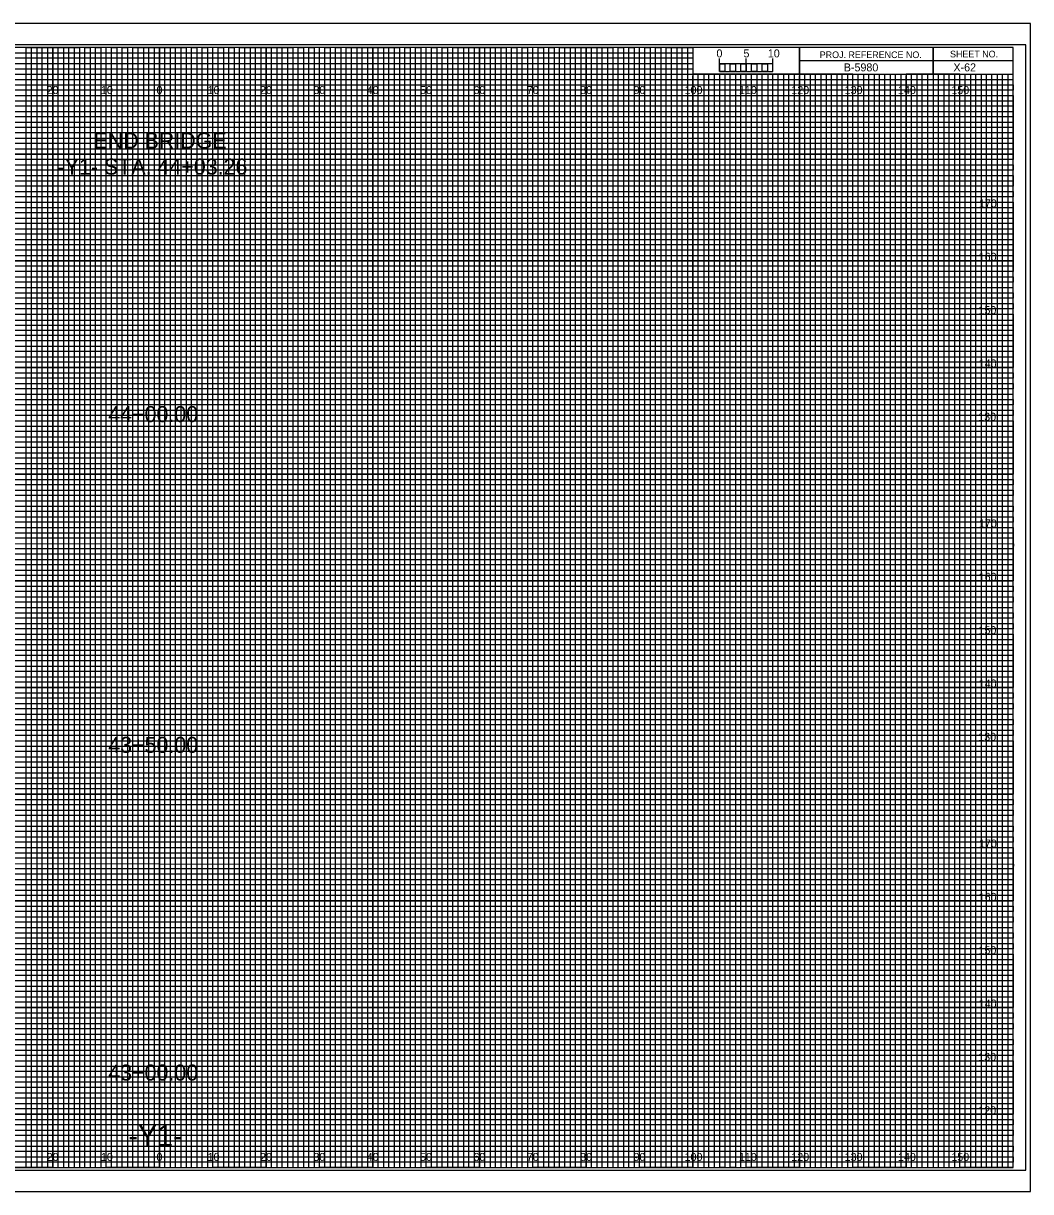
# Model space of a CAD drawing. Extents: x -13 to 323, y -5 to 4834.
# Drawn here: x 134.5 to 323.3, y 3515.5 to 3734.5 of the extents above; entities that cross this region are included whole.
import ezdxf

# ---------------------------------------------------------------- set-up
doc = ezdxf.new("R2010")
doc.units = 0
for name, color, linetype in [('Exist CMT Pavement', 7, 'Continuous'), ('Exist Cross Section Cell', 7, 'Continuous'), ('Exist XS Center Line Elevation Label', 7, 'Continuous'), ('Exist XS Ground Line', 7, 'Continuous'), ('Prop CMT Pvmt Course 1', 7, 'Continuous'), ('Prop CMT Pvmt Course 1 Wedge', 7, 'Continuous'), ('Prop CMT Pvmt Course 2', 7, 'Continuous'), ('Prop CMT Pvmt Course 2 Wedge', 7, 'Continuous'), ('Prop CMT Pvmt Course 3', 7, 'Continuous'), ('Prop CMT Pvmt Course 3 Wedge', 7, 'Continuous'), ('Prop CMT Pvmt Surface', 7, 'Continuous'), ('Prop CMT Pvmt Surface Shoulder', 7, 'Continuous'), ('Prop CMT Shld Paved Course 1', 7, 'Continuous'), ('Prop CMT Shld Paved Course 2', 7, 'Continuous'), ('Prop CMT Shld Paved Course 3', 7, 'Continuous'), ('Prop CMT Slope Grass', 7, 'Continuous'), ('Prop CMT Subgrade Earthwork', 7, 'Continuous')]:
    doc.layers.add(name, color=color, linetype=linetype)

msp = doc.modelspace()

# ---------------------------------------------------------------- linework, layer by layer
at = {"layer": 'Exist XS Center Line Elevation Label'}
for points in [[(125, 3520), (135, 3520), (135, 3730), (145, 3730), (145, 3520), (155, 3520), (155, 3730), (165, 3730), (165, 3520), (175, 3520), (175, 3730), (185, 3730), (185, 3520), (195, 3520), (195, 3730), (205, 3730), (205, 3520), (215, 3520), (215, 3730), (225, 3730), (225, 3520), (235, 3520), (235, 3730), (245, 3730), (245, 3520), (255, 3520), (255, 3730), (259.93, 3730), (260, 3730), (260, 3725), (264.99, 3725), (264.99, 3520), (275, 3520), (275, 3725), (285, 3725), (285, 3520), (295, 3520), (295, 3725), (305, 3725), (305, 3520), (315, 3520), (315, 3725)], [(0, 3725), (275, 3725)], [(0, 3705), (320, 3705), (320, 3715), (0, 3715)], [(0, 3685), (320, 3685), (320, 3695), (0, 3695)], [(0, 3665), (320, 3665), (320, 3675), (0, 3675)], [(0, 3645), (320, 3645), (320, 3655), (0, 3655)], [(0, 3625), (320, 3625), (320, 3635), (0, 3635)], [(0, 3605), (320, 3605), (320, 3615), (0, 3615)], [(0, 3585), (320, 3585), (320, 3595), (0, 3595)], [(0, 3565), (320, 3565), (320, 3575), (0, 3575)], [(0, 3545), (320, 3545), (320, 3555), (0, 3555)], [(0, 3525), (320, 3525), (320, 3535), (0, 3535)]]:
    msp.add_lwpolyline(points, dxfattribs=at)
at = {"layer": 'Exist XS Ground Line'}
for p, q in [((150, 3730), (140, 3730)), ((140, 3730), (140, 3520)), ((150, 3520), (150, 3730)), ((170, 3730), (160, 3730)), ((160, 3730), (160, 3520)), ((170, 3520), (170, 3730)), ((190, 3730), (180, 3730)), ((180, 3730), (180, 3520)), ((190, 3520), (190, 3730)), ((210, 3730), (200, 3730)), ((200, 3730), (200, 3520)), ((210, 3520), (210, 3730)), ((230, 3730), (220, 3730)), ((220, 3730), (220, 3520)), ((230, 3520), (230, 3730)), ((250, 3730), (240, 3730)), ((240, 3730), (240, 3520)), ((250, 3520), (250, 3730)), ((260, 3730), (260, 3520)), ((270, 3520), (270, 3725)), ((290, 3725), (280, 3725)), ((280, 3725), (280, 3520)), ((290, 3520), (290, 3725)), ((310, 3725), (300, 3725)), ((300, 3725), (300, 3520)), ((310, 3520), (310, 3725)), ((140, 3520), (130, 3520)), ((160, 3520), (150, 3520)), ((180, 3520), (170, 3520)), ((200, 3520), (190, 3520)), ((220, 3520), (210, 3520)), ((240, 3520), (230, 3520)), ((260, 3520), (250, 3520)), ((280, 3520), (270, 3520)), ((300, 3520), (290, 3520)), ((320, 3520), (310, 3520)), ((320, 3520), (320, 3520))]:
    msp.add_line(p, q, dxfattribs=at)
for points in [[(0, 3720), (320, 3720), (320, 3710), (0, 3710)], [(0, 3700), (320, 3700), (320, 3690), (0, 3690)], [(0, 3680), (320, 3680), (320, 3670), (0, 3670)], [(0, 3660), (320, 3660), (320, 3650), (0, 3650)], [(0, 3640), (320, 3640), (320, 3630), (0, 3630)], [(0, 3620), (320, 3620), (320, 3610), (0, 3610)], [(0, 3600), (320, 3600), (320, 3590), (0, 3590)], [(0, 3580), (320, 3580), (320, 3570), (0, 3570)], [(0, 3560), (320, 3560), (320, 3550), (0, 3550)], [(0, 3540), (320, 3540), (320, 3530), (0, 3530)]]:
    msp.add_lwpolyline(points, dxfattribs=at)
at = {"layer": 'Prop CMT Pvmt Course 1'}
for p, q in [((267, 3725), (266.01, 3725)), ((266.01, 3725), (266.01, 3520)), ((267, 3520), (267, 3725)), ((269, 3725), (268, 3725)), ((268, 3725), (268, 3520)), ((269, 3520), (269, 3725)), ((266.01, 3520), (265, 3520)), ((268, 3520), (267, 3520))]:
    msp.add_line(p, q, dxfattribs=at)
for points in [[(135, 3520), (136, 3520), (136, 3730), (137, 3730), (137, 3520)], [(137, 3520), (138, 3520), (138, 3730), (139, 3730), (139, 3520)], [(140, 3520), (141, 3520), (141, 3730), (142, 3730), (142, 3520)], [(142, 3520), (143, 3520), (143, 3730), (144, 3730), (144, 3520)], [(145, 3520), (146, 3520), (146, 3730), (147, 3730), (147, 3520)], [(147, 3520), (148, 3520), (148, 3730), (149, 3730), (149, 3520)], [(150, 3520), (151, 3520), (151, 3730), (152, 3730), (152, 3520)], [(152, 3520), (153, 3520), (153, 3730), (154, 3730), (154, 3520)], [(155, 3520), (156, 3520), (156, 3730), (157, 3730), (157, 3520)], [(157, 3520), (158, 3520), (158, 3730), (159, 3730), (159, 3520)], [(160, 3520), (161, 3520), (161, 3730), (162, 3730), (162, 3520)], [(162, 3520), (163, 3520), (163, 3730), (164, 3730), (164, 3520)], [(165, 3520), (166, 3520), (166, 3730), (167, 3730), (167, 3520)], [(167, 3520), (168, 3520), (168, 3730), (169, 3730), (169, 3520)], [(170, 3520), (171, 3520), (171, 3730), (172, 3730), (172, 3520)], [(172, 3520), (173, 3520), (173, 3730), (174, 3730), (174, 3520)], [(175, 3520), (176, 3520), (176, 3730), (177, 3730), (177, 3520)], [(177, 3520), (178, 3520), (178, 3730), (179, 3730), (179, 3520)], [(180, 3520), (181, 3520), (181, 3730), (182, 3730), (182, 3520)], [(182, 3520), (183, 3520), (183, 3730), (184, 3730), (184, 3520)], [(185, 3520), (186, 3520), (186, 3730), (187, 3730), (187, 3520)], [(187, 3520), (188, 3520), (188, 3730), (189, 3730), (189, 3520)], [(190, 3520), (191, 3520), (191, 3730), (192, 3730), (192, 3520)], [(192, 3520), (193, 3520), (193, 3730), (194, 3730), (194, 3520)], [(195, 3520), (196, 3520), (196, 3730), (197, 3730), (197, 3520)], [(197, 3520), (198, 3520), (198, 3730), (199, 3730), (199, 3520)], [(200, 3520), (201, 3520), (201, 3730), (202, 3730), (202, 3520)], [(202, 3520), (203, 3520), (203, 3730), (204, 3730), (204, 3520)], [(205, 3520), (206, 3520), (206, 3730), (207, 3730), (207, 3520)], [(207, 3520), (208, 3520), (208, 3730), (209, 3730), (209, 3520)], [(210, 3520), (211, 3520), (211, 3730), (212, 3730), (212, 3520)], [(212, 3520), (213, 3520), (213, 3730), (214, 3730), (214, 3520)], [(215, 3520), (216, 3520), (216, 3730), (217, 3730), (217, 3520)], [(217, 3520), (218, 3520), (218, 3730), (219, 3730), (219, 3520)], [(220, 3520), (221, 3520), (221, 3730), (222, 3730), (222, 3520)], [(222, 3520), (223, 3520), (223, 3730), (224, 3730), (224, 3520)], [(225, 3520), (226, 3520), (226, 3730), (227, 3730), (227, 3520)], [(227, 3520), (228, 3520), (228, 3730), (229, 3730), (229, 3520)], [(230, 3520), (231, 3520), (231, 3730), (232, 3730), (232, 3520)], [(232, 3520), (233, 3520), (233, 3730), (234, 3730), (234, 3520)], [(235, 3520), (236, 3520), (236, 3730), (237, 3730), (237, 3520)], [(237, 3520), (238, 3520), (238, 3730), (239, 3730), (239, 3520)], [(240, 3520), (241, 3520), (241, 3730), (242, 3730), (242, 3520)], [(242, 3520), (243, 3520), (243, 3730), (244, 3730), (244, 3520)], [(245, 3520), (246, 3520), (246, 3730), (247, 3730), (247, 3520)], [(247, 3520), (248, 3520), (248, 3730), (249, 3730), (249, 3520)], [(250, 3520), (251, 3520), (251, 3730), (252, 3730), (252, 3520)], [(252, 3520), (253, 3520), (253, 3730), (254, 3730), (254, 3520)], [(255, 3520), (256, 3520), (256, 3730), (257, 3730), (257, 3520)], [(257, 3520), (258, 3520), (258, 3730), (259, 3730), (259, 3520)], [(260, 3520), (261, 3520), (261, 3725), (262.02, 3725), (262.02, 3520)], [(262, 3520), (263, 3520), (263, 3725), (263.99, 3725), (263.99, 3520)], [(270, 3520), (270.98, 3520), (270.98, 3725), (272, 3725), (272, 3520)], [(272, 3520), (273, 3520), (273, 3725), (274.05, 3725), (274.05, 3520)], [(275, 3520), (276, 3520), (276, 3725), (277, 3725), (277, 3520)], [(277, 3520), (278, 3520), (278, 3725), (279, 3725), (279, 3520)], [(280, 3520), (281, 3520), (281, 3725), (282, 3725), (282, 3520)], [(282, 3520), (283, 3520), (283, 3725), (284, 3725), (284, 3520)], [(285, 3520), (286, 3520), (286, 3725), (287, 3725), (287, 3520)], [(287, 3520), (288, 3520), (288, 3725), (289, 3725), (289, 3520)], [(290, 3520), (291, 3520), (291, 3725), (292, 3725), (292, 3520)], [(292, 3520), (293, 3520), (293, 3725), (294, 3725), (294, 3520)], [(295, 3520), (296, 3520), (296, 3725), (297, 3725), (297, 3520)], [(297, 3520), (298, 3520), (298, 3725), (299, 3725), (299, 3520)], [(300, 3520), (301, 3520), (301, 3725), (302, 3725), (302, 3520)], [(302, 3520), (303, 3520), (303, 3725), (304, 3725), (304, 3520)], [(305, 3520), (306, 3520), (306, 3725), (307, 3725), (307, 3520)], [(307, 3520), (308, 3520), (308, 3725), (309, 3725), (309, 3520)], [(310, 3520), (311, 3520), (311, 3725), (312, 3725), (312, 3520)], [(312, 3520), (313, 3520), (313, 3725), (314, 3725), (314, 3520)], [(315, 3520), (316, 3520), (316, 3725), (317, 3725), (317, 3520)], [(317, 3520), (318, 3520), (318, 3725), (319, 3725), (319, 3520)]]:
    msp.add_lwpolyline(points, dxfattribs=at)
at = {"layer": 'Prop CMT Pvmt Course 2'}
for p, q in [((323.3, 3734.5), (-13.4, 3734.5)), ((-13.4, 3515.5), (323.3, 3515.5))]:
    msp.add_line(p, q, dxfattribs=at)
at = {"layer": 'Prop CMT Pvmt Surface Shoulder'}
for p, q in [((305, 3730), (305, 3725)), ((305, 3725), (305, 3730)), ((280, 3727.5), (280, 3725)), ((320, 3727.49), (280, 3727.49)), ((280, 3725), (320, 3725))]:
    msp.add_line(p, q, dxfattribs=at)
for points in [[(320, 3730), (0, 3730), (0, 3520), (320, 3520)], [(280, 3730), (260, 3730), (260, 3725.03), (280, 3725.03)], [(320, 3730), (280, 3730), (280, 3725), (320, 3725)]]:
    msp.add_lwpolyline(points, close=True, dxfattribs=at)
at = {"layer": 'Prop CMT Shld Paved Course 1'}
msp.add_lwpolyline([(-13.4, 3515.5), (323.3, 3515.5), (323.3, 3734.5), (-13.4, 3734.5)], close=True, dxfattribs=at)
at = {"layer": 'Prop CMT Shld Paved Course 2'}
msp.add_lwpolyline([(-10.8, 3519.5), (322.4, 3519.5), (322.4, 3730.5), (-10.8, 3730.5)], close=True, dxfattribs=at)
at = {"layer": 'Prop CMT Shld Paved Course 3'}
for p, q in [((140, 3520), (140, 3730)), ((150, 3520), (150, 3730)), ((160, 3520), (160, 3730)), ((170, 3520), (170, 3730)), ((180, 3520), (180, 3730)), ((190, 3520), (190, 3730)), ((200, 3520), (200, 3730)), ((210, 3520), (210, 3730)), ((220, 3520), (220, 3730)), ((230, 3520), (230, 3730)), ((240, 3520), (240, 3730)), ((250, 3520), (250, 3730)), ((260, 3520), (260, 3724.69)), ((270, 3520), (270, 3724.69)), ((280, 3520), (280, 3724.69)), ((290, 3520), (290, 3724.69)), ((300, 3520), (300, 3724.69)), ((310, 3520), (310, 3724.69)), ((0, 3720), (320, 3720)), ((0, 3710), (320, 3710)), ((0, 3700), (320, 3700)), ((0, 3690), (320, 3690)), ((0, 3680), (320, 3680)), ((0, 3670), (320, 3670)), ((0, 3660), (320, 3660)), ((0, 3650), (320, 3650)), ((0, 3640), (320, 3640)), ((0, 3630), (320, 3630)), ((0, 3620), (320, 3620)), ((0, 3610), (320, 3610)), ((0, 3600), (320, 3600)), ((0, 3590), (320, 3590)), ((0, 3580), (320, 3580)), ((0, 3570), (320, 3570)), ((0, 3560), (320, 3560)), ((0, 3550), (320, 3550)), ((0, 3540), (320, 3540)), ((0, 3530), (320, 3530))]:
    msp.add_line(p, q, dxfattribs=at)
at = {"layer": 'Prop CMT Slope Grass'}
for p, q in [((0, 3729), (260, 3729)), ((260, 3727.98), (0, 3727.98)), ((260, 3729), (260, 3727.98)), ((0, 3727), (260, 3727)), ((260, 3725.89), (0, 3725.89)), ((260, 3727), (260, 3725.89)), ((0, 3724), (320, 3724))]:
    msp.add_line(p, q, dxfattribs=at)
for points in [[(0, 3723), (270, 3723), (320, 3723), (320, 3722), (0, 3722)], [(0, 3721), (320, 3721), (320, 3719), (0, 3719)], [(0, 3718), (320, 3718), (320, 3717), (0, 3716.98)], [(0, 3716), (320, 3716), (320, 3714), (0, 3714)], [(0, 3713), (320, 3713), (320, 3712), (0, 3712)], [(0, 3711), (320, 3711), (320, 3709), (0, 3709)], [(0, 3708), (320, 3708), (320, 3707), (0, 3707)], [(0, 3706), (320, 3706), (320, 3704), (0, 3704)], [(0, 3703), (320, 3703), (320, 3702), (0, 3702)], [(0, 3701), (320, 3701), (320, 3699), (0, 3699)], [(0, 3698), (320, 3698), (320, 3697), (0, 3697)], [(0, 3696), (320, 3696), (320, 3693.95), (320, 3693), (320, 3692), (0, 3692)], [(0, 3694), (320, 3694), (320, 3693), (0, 3693)], [(0, 3691), (320, 3691), (320, 3689), (0, 3689.03)], [(0, 3689.03), (320, 3689), (320, 3688), (0, 3688)], [(0, 3687), (320, 3687), (320, 3686), (0, 3686)], [(0, 3684), (320, 3684), (320, 3683), (0, 3683)], [(0, 3682), (320, 3682), (320, 3681), (0, 3681)], [(-0.07, 3678.89), (320, 3678.89), (320, 3677.88), (-0.07, 3677.88)], [(0, 3677), (320, 3677), (320, 3676), (0, 3676)], [(0, 3674), (320, 3674), (320, 3673), (0, 3673)], [(0, 3672), (320, 3672), (320, 3671), (0, 3671)], [(0, 3669), (320, 3669), (320, 3668), (0, 3668)], [(0, 3667), (320, 3667), (320, 3666), (0, 3666)], [(0, 3664), (320, 3664), (320, 3663), (0, 3663)], [(0, 3662), (320, 3662), (320, 3661), (0, 3661)], [(0, 3659), (320, 3659), (319.99, 3657.98), (0, 3658)], [(0, 3657), (320, 3657), (320, 3656), (0, 3656)], [(0, 3654), (320, 3654), (320, 3653), (0, 3653)], [(0, 3652), (320, 3652), (320, 3651), (0, 3651)], [(0, 3649), (320, 3649), (320, 3648), (0, 3648)], [(0, 3647), (320, 3647), (320, 3646), (0, 3646)], [(0, 3644), (320, 3644), (320, 3643), (0, 3643)], [(0, 3642), (320, 3642), (320, 3641), (0, 3641)], [(0, 3639), (320, 3639), (320, 3638), (0, 3638)], [(0, 3636.99), (320.07, 3636.91), (320, 3636), (0, 3636)], [(0, 3634), (320, 3634), (320, 3633), (0, 3633)], [(0, 3632), (320, 3632), (320, 3631), (0, 3631)], [(0, 3629), (320, 3629), (320, 3628), (0, 3628)], [(0, 3627), (320, 3627), (320, 3626), (0, 3626)], [(0, 3624), (320, 3624), (320, 3623), (0, 3623)], [(0, 3622), (320, 3622), (320, 3621), (0, 3621)], [(0, 3619), (320, 3619), (320, 3618), (0, 3618)], [(0, 3617), (320, 3617), (320, 3616), (0, 3616)], [(0, 3614), (320, 3614), (320, 3613), (0, 3613)], [(0, 3612), (320, 3612), (320, 3611), (0, 3611)], [(0, 3609), (320, 3609), (320, 3608), (0, 3608)], [(0, 3607), (320, 3607), (320, 3606), (0, 3606)], [(0, 3604), (320, 3604), (320, 3603), (0, 3603)], [(0, 3602), (320, 3602), (320, 3601), (0, 3601)], [(0, 3599), (320, 3599), (319.99, 3597.98), (0, 3598)], [(0, 3597), (320, 3597), (320, 3596), (0, 3596)], [(0, 3594), (320, 3594), (320, 3593), (0, 3593)], [(0, 3592), (320, 3592), (320, 3591), (0, 3591)], [(0, 3589), (320, 3589), (320, 3588), (0, 3588)], [(0, 3587), (320, 3587), (320, 3586), (0, 3586)], [(0, 3584), (320, 3584), (320, 3583), (0, 3583)], [(0, 3582), (320, 3582), (320, 3581), (0, 3581)], [(0, 3579), (320, 3579), (320, 3578), (0, 3578)], [(0, 3576.99), (320.07, 3576.91), (320, 3576), (0, 3576)], [(0, 3574), (320, 3574), (320, 3573), (0, 3573)], [(0, 3572), (320, 3572), (320, 3571), (0, 3571)], [(0, 3569), (320, 3569), (320, 3568), (0, 3568)], [(0, 3567), (320, 3567), (320, 3566), (0, 3566)], [(0, 3564), (320, 3564), (320, 3563), (0, 3563)], [(0, 3562), (320, 3562), (320, 3561), (0, 3561)], [(0, 3559), (320, 3559), (320, 3558), (0, 3558)], [(0, 3557), (320, 3557), (320, 3556), (0, 3556)], [(0, 3554), (320, 3554), (320, 3553), (0, 3553)], [(0, 3552), (320, 3552), (320, 3551), (0, 3551)], [(0, 3549), (320, 3549), (320, 3548), (0, 3548)], [(0, 3547), (320, 3547), (320, 3546), (0, 3546)], [(0, 3544), (320, 3544), (320, 3543), (0, 3543)], [(0, 3542), (320, 3542), (320, 3541), (0, 3541)], [(0, 3539), (320, 3539), (320, 3538), (0, 3538)], [(0, 3537), (320, 3537), (320, 3536), (0, 3536)], [(0, 3534), (320, 3534), (320, 3533), (0, 3533)], [(0, 3532), (320, 3532), (320, 3531), (0, 3531)], [(0, 3529), (320, 3529), (320, 3528), (0, 3528)], [(0, 3527), (320, 3527), (320, 3526), (0, 3526)], [(0, 3524), (320, 3524), (320, 3523), (0, 3523)], [(0, 3522), (320, 3522), (320, 3521), (0, 3521)]]:
    msp.add_lwpolyline(points, dxfattribs=at)
at = {"layer": 'Prop CMT Subgrade Earthwork'}
for p, q in [((265, 3725.49), (265, 3727.9)), ((265, 3726.9), (265, 3727.9)), ((270, 3725.49), (270, 3727.9)), ((275, 3725.49), (275, 3727.9)), ((275, 3726.9), (275, 3727.9))]:
    msp.add_line(p, q, dxfattribs=at)
for points in [[(275, 3726.9), (265, 3726.9), (265, 3725.49), (275, 3725.49)], [(265, 3726.9), (266, 3726.9), (266, 3725.49), (265, 3725.49)], [(267, 3726.9), (268, 3726.9), (268, 3725.49), (267, 3725.49)], [(269, 3726.9), (270, 3726.9), (270, 3725.49), (269, 3725.49)], [(271, 3726.9), (272, 3726.9), (272, 3725.49), (271, 3725.49)], [(273, 3726.9), (274, 3726.9), (274, 3725.49), (273, 3725.49)]]:
    msp.add_lwpolyline(points, close=True, dxfattribs=at)

# ---------------------------------------------------------------- texts
at = {"layer": 'Exist CMT Pavement'}
msp.add_text('-Y1-', height=4, dxfattribs=at).set_placement((154.21, 3524))
at = {"layer": 'Exist Cross Section Cell'}
for s, p in [('20', (138.86, 3721.25)), ('10', (149.04, 3721.25)), ('0', (159.45, 3721.25)), ('0', (159.45, 3721.25)), ('10', (169.04, 3721.25)), ('20', (178.86, 3721.25)), ('30', (188.86, 3721.25)), ('40', (198.86, 3721.25)), ('50', (208.86, 3721.25)), ('60', (218.86, 3721.25)), ('70', (228.86, 3721.25)), ('80', (238.86, 3721.25)), ('90', (248.86, 3721.25)), ('100', (258.44, 3721.25)), ('110', (268.62, 3721.25)), ('120', (278.44, 3721.25)), ('130', (288.44, 3721.25)), ('140', (298.44, 3721.25)), ('150', (308.44, 3721.25)), ('20', (138.86, 3521.25)), ('10', (149.04, 3521.25)), ('0', (159.45, 3521.25)), ('0', (159.45, 3521.25)), ('10', (169.04, 3521.25)), ('20', (178.86, 3521.25)), ('30', (188.86, 3521.25)), ('40', (198.86, 3521.25)), ('50', (208.86, 3521.25)), ('60', (218.86, 3521.25)), ('70', (228.86, 3521.25)), ('80', (238.86, 3521.25)), ('90', (248.86, 3521.25)), ('100', (258.44, 3521.25)), ('110', (268.62, 3521.25)), ('120', (278.44, 3521.25)), ('130', (288.44, 3521.25)), ('140', (298.44, 3521.25)), ('150', (308.44, 3521.25))]:
    msp.add_text(s, height=1.5, dxfattribs=at).set_placement(p)
at = {"layer": 'Prop CMT Pvmt Course 1 Wedge'}
for s, p in [('END BRIDGE', (147.63, 3711.03)), ('-Y1- STA. 44+03.26', (140.92, 3706.15)), ('44+00.00', (150.41, 3659.76)), ('43+50.00', (150.41, 3597.75)), ('43+00.00', (150.41, 3536.33))]:
    msp.add_text(s, height=3, dxfattribs=at).set_placement(p)
at = {"layer": 'Prop CMT Pvmt Course 2 Wedge'}
msp.add_text('X-62', height=1.5, dxfattribs=at).set_placement((308.83, 3725.5))
at = {"layer": 'Prop CMT Pvmt Course 3'}
for s, p in [('170', (313.61, 3700)), ('160', (313.57, 3690)), ('150', (313.52, 3680)), ('140', (313.57, 3670)), ('130', (313.49, 3660)), ('170', (313.61, 3640)), ('160', (313.57, 3630)), ('150', (313.52, 3620)), ('140', (313.57, 3610)), ('130', (313.49, 3600)), ('170', (313.61, 3580)), ('160', (313.57, 3570)), ('150', (313.52, 3560)), ('140', (313.57, 3550)), ('130', (313.49, 3540)), ('120', (313.5, 3530))]:
    msp.add_text(s, height=1.5, dxfattribs=at).set_placement(p)
at = {"layer": 'Prop CMT Pvmt Course 3 Wedge'}
msp.add_text('B-5980', height=1.5, dxfattribs=at).set_placement((288.28, 3725.5))
at = {"layer": 'Prop CMT Pvmt Surface'}
for s, p in [('5', (269.47, 3728.12)), ('10', (274.04, 3728.12))]:
    msp.add_text(s, height=1.5, dxfattribs=at).set_placement(p)
at = {"layer": 'Prop CMT Pvmt Surface Shoulder'}
for s, p in [('PROJ. REFERENCE NO.', (283.77, 3727.99)), ('SHEET NO.', (308.19, 3728.12))]:
    msp.add_text(s, height=1.25, dxfattribs=at).set_placement(p)
at = {"layer": 'Prop CMT Subgrade Earthwork'}
msp.add_text('0', height=1.5, dxfattribs=at).set_placement((264.41, 3728.12))

doc.saveas('drawing.dxf')
